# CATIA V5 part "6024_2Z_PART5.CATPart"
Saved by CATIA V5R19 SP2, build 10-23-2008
Part number: 6024_2Z_PART5
Bounding box of the stored display mesh (mm): x 4.872 to 23.128, y 65.924 to 84.076, z -9.076 to 9.076
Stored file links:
  G:\EU_thinkMotion\CFAO_2010\MMS_groupe2\MMS_groupe2\OK\nrosalie\nrosalie_cfao_support_d_arme_legere_final\6024_2Z_PART5.CATPart
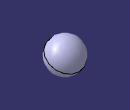
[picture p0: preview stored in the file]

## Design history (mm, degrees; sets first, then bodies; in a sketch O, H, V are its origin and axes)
Set1
  Point1: (0, 0, 0)
  Point2: (1, 0, 0)
  Point3: (0, 1, 0)
  Plane1: type 3Points, Element1 Point1, Element2 Point2, Element3 Point3
Body1 (main body)
  Sketch1 on Plane1, origin (0, 0, 0), H (1, 0, 0), V (0, 1, 0)
    arc A1 centre (14, 75) radius 9.128 from (23.128, 75) to (4.872, 75) ccw
    point P1 (23.128, 75)
    point P2 (4.872, 75)
    line L1 (23.128, 75) -> (4.872, 75)
    point P3 (23.128, 75)
    point P4 (4.872, 75)
    axis line L2 (23.128, 75) -> (4.872, 75)
    point P5 (23.128, 75)
    point P6 (4.872, 75)
    point P7 (23.128, 75)
    point P8 (4.872, 75)
    coincidence: P5 P7, P6 P8
  Shaft1: profile Sketch1, axis Sketch1.L2, angle 360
